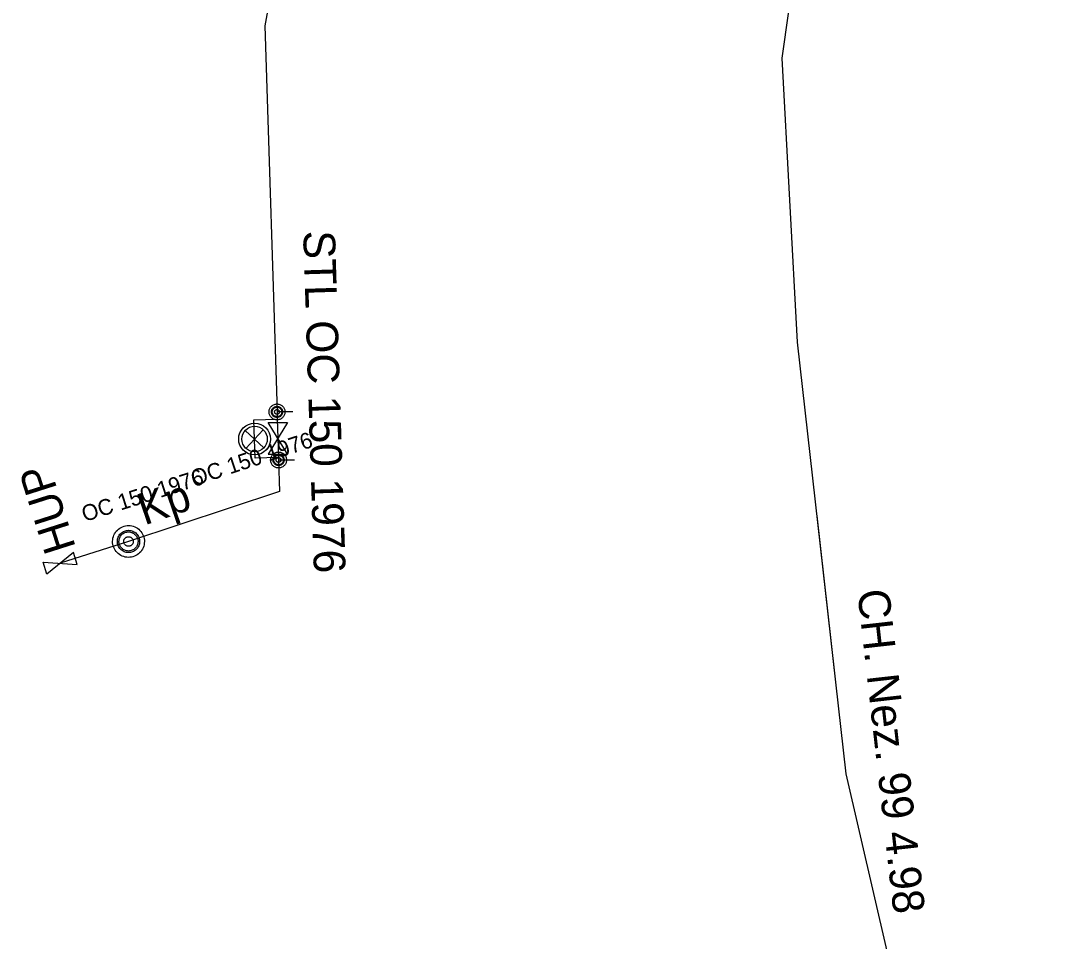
# Model space of a CAD drawing. Extents: x -743325 to -742825, y -1051501 to -1050981.
# Drawn here: x -743099.05 to -743066.36, y -1051247.7 to -1051218.76 of the extents above; entities that cross this region are included whole.
import ezdxf

# ---------------------------------------------------------------- set-up
doc = ezdxf.new("R2010")
doc.units = 0
for name, color, linetype in [('NT OP Chráni_ka - provoz', 7, 'Continuous'), ('NT Úsek plynovodu - provoz', 7, 'Continuous'), ('ST Kapák - provoz_popis', 7, 'Continuous'), ('ST Ochoz plynovodu - provoz', 7, 'Continuous'), ('ST Úsek p_ípojky - provoz', 7, 'Continuous'), ('ST Úsek plynovodu - provoz', 7, 'Continuous'), ('ST_HUP_24_popis', 7, 'Continuous'), ('Vrstva 1', 7, 'Continuous')]:
    doc.layers.add(name, color=color, linetype=linetype)

msp = doc.modelspace()

# ---------------------------------------------------------------- linework, layer by layer
at = {"layer": 'NT OP Chráni_ka - provoz'}
msp.add_lwpolyline([(-743074.013, -1051234.317), (-743073.456, -1051239.266)], dxfattribs=at)
at = {"layer": 'NT Úsek plynovodu - provoz'}
msp.add_lwpolyline([(-743070.968, -1051164.821), (-743071.535, -1051165.016), (-743070.085, -1051169.589), (-743067.096, -1051178.869), (-743066.357, -1051181.989), (-743073.395, -1051209.661), (-743074.036, -1051212.311), (-743075.117, -1051219.935), (-743074.627, -1051228.857), (-743073.099, -1051242.438), (-743069.652, -1051257.351)], dxfattribs=at)
at = {"layer": 'ST Ochoz plynovodu - provoz'}
msp.add_lwpolyline([(-743090.917, -1051232.485), (-743090.947, -1051232.485), (-743091.68, -1051232.508), (-743091.699, -1051231.908), (-743091.718, -1051231.308), (-743090.985, -1051231.285)], dxfattribs=at)
at = {"layer": 'ST Úsek p_ípojky - provoz'}
for points in [[(-743090.913, -1051233.556), (-743095.664, -1051235.128)], [(-743095.664, -1051235.128), (-743097.815, -1051235.814)]]:
    msp.add_lwpolyline(points, dxfattribs=at)
at = {"layer": 'ST Úsek plynovodu - provoz'}
for points in [[(-743072.447, -1051184.993), (-743072.908, -1051184.597), (-743077.116, -1051180.977), (-743077.49, -1051180.777), (-743085.06, -1051188.896), (-743089.578, -1051208.662), (-743091.275, -1051218.341), (-743091.375, -1051218.913)], [(-743091.375, -1051218.913), (-743090.992, -1051231.055), (-743090.985, -1051231.285), (-743090.966, -1051231.885)], [(-743090.966, -1051231.885), (-743090.947, -1051232.485), (-743090.944, -1051232.567), (-743090.913, -1051233.556)]]:
    msp.add_lwpolyline(points, dxfattribs=at)
at = {"layer": 'Vrstva 1'}
for p, q in [((-743090.492, -1051231.055), (-743090.992, -1051231.055)), ((-743091.266, -1051231.385), (-743090.666, -1051231.385)), ((-743090.666, -1051231.385), (-743091.266, -1051232.385)), ((-743090.666, -1051232.385), (-743091.266, -1051231.385)), ((-743091.992, -1051231.635), (-743091.406, -1051232.181)), ((-743091.426, -1051231.615), (-743091.972, -1051232.201)), ((-743091.266, -1051232.385), (-743090.666, -1051232.385)), ((-743090.444, -1051232.567), (-743090.944, -1051232.567))]:
    msp.add_line(p, q, dxfattribs=at)
for points in [[(-743090.742, -1051231.043), (-743090.742, -1051231.067), (-743090.745, -1051231.092), (-743090.749, -1051231.116), (-743090.757, -1051231.139), (-743090.766, -1051231.162), (-743090.777, -1051231.183), (-743090.791, -1051231.204), (-743090.807, -1051231.223), (-743090.824, -1051231.24), (-743090.843, -1051231.256), (-743090.863, -1051231.269), (-743090.885, -1051231.281), (-743090.908, -1051231.29), (-743090.931, -1051231.298), (-743090.955, -1051231.302), (-743090.98, -1051231.305), (-743091.005, -1051231.305), (-743091.029, -1051231.302), (-743091.053, -1051231.298), (-743091.077, -1051231.29), (-743091.099, -1051231.281), (-743091.121, -1051231.269), (-743091.141, -1051231.256), (-743091.16, -1051231.24), (-743091.178, -1051231.223), (-743091.193, -1051231.204), (-743091.207, -1051231.183), (-743091.218, -1051231.162), (-743091.228, -1051231.139), (-743091.235, -1051231.116), (-743091.24, -1051231.092), (-743091.242, -1051231.067), (-743091.242, -1051231.043), (-743091.24, -1051231.018), (-743091.235, -1051230.994), (-743091.228, -1051230.971), (-743091.218, -1051230.948), (-743091.207, -1051230.926), (-743091.193, -1051230.906), (-743091.178, -1051230.887), (-743091.16, -1051230.869), (-743091.141, -1051230.854), (-743091.121, -1051230.84), (-743091.099, -1051230.829), (-743091.077, -1051230.819), (-743091.053, -1051230.812), (-743091.029, -1051230.807), (-743091.005, -1051230.805), (-743090.98, -1051230.805), (-743090.955, -1051230.807), (-743090.931, -1051230.812), (-743090.908, -1051230.819), (-743090.885, -1051230.829), (-743090.863, -1051230.84), (-743090.843, -1051230.854), (-743090.824, -1051230.869), (-743090.807, -1051230.887), (-743090.791, -1051230.906), (-743090.777, -1051230.926), (-743090.766, -1051230.948), (-743090.757, -1051230.971), (-743090.749, -1051230.994), (-743090.745, -1051231.018)], [(-743091.001, -1051230.88), (-743090.984, -1051230.88), (-743090.967, -1051230.881), (-743090.95, -1051230.885), (-743090.933, -1051230.89), (-743090.917, -1051230.896), (-743090.902, -1051230.905), (-743090.888, -1051230.914), (-743090.875, -1051230.925), (-743090.862, -1051230.937), (-743090.851, -1051230.95), (-743090.842, -1051230.965), (-743090.834, -1051230.98), (-743090.827, -1051230.996), (-743090.822, -1051231.012), (-743090.819, -1051231.029), (-743090.817, -1051231.046), (-743090.817, -1051231.063), (-743090.819, -1051231.081), (-743090.822, -1051231.097), (-743090.827, -1051231.114), (-743090.834, -1051231.13), (-743090.842, -1051231.145), (-743090.851, -1051231.159), (-743090.862, -1051231.172), (-743090.875, -1051231.185), (-743090.888, -1051231.196), (-743090.902, -1051231.205), (-743090.917, -1051231.213), (-743090.933, -1051231.22), (-743090.95, -1051231.225), (-743090.967, -1051231.228), (-743090.984, -1051231.23), (-743091.001, -1051231.23), (-743091.018, -1051231.228), (-743091.035, -1051231.225), (-743091.051, -1051231.22), (-743091.067, -1051231.213), (-743091.082, -1051231.205), (-743091.097, -1051231.196), (-743091.11, -1051231.185), (-743091.122, -1051231.172), (-743091.133, -1051231.159), (-743091.143, -1051231.145), (-743091.151, -1051231.13), (-743091.157, -1051231.114), (-743091.162, -1051231.097), (-743091.165, -1051231.081), (-743091.167, -1051231.063), (-743091.167, -1051231.046), (-743091.165, -1051231.029), (-743091.162, -1051231.012), (-743091.157, -1051230.996), (-743091.151, -1051230.98), (-743091.143, -1051230.965), (-743091.133, -1051230.95), (-743091.122, -1051230.937), (-743091.11, -1051230.925), (-743091.097, -1051230.914), (-743091.082, -1051230.905), (-743091.067, -1051230.896), (-743091.051, -1051230.89), (-743091.035, -1051230.885), (-743091.018, -1051230.881)], [(-743090.985, -1051231.205), (-743091, -1051231.205), (-743091.014, -1051231.203), (-743091.029, -1051231.201), (-743091.043, -1051231.196), (-743091.056, -1051231.191), (-743091.069, -1051231.184), (-743091.082, -1051231.175), (-743091.093, -1051231.166), (-743091.103, -1051231.156), (-743091.113, -1051231.144), (-743091.121, -1051231.132), (-743091.128, -1051231.119), (-743091.134, -1051231.105), (-743091.138, -1051231.091), (-743091.141, -1051231.077), (-743091.142, -1051231.062), (-743091.142, -1051231.047), (-743091.141, -1051231.033), (-743091.138, -1051231.018), (-743091.134, -1051231.004), (-743091.128, -1051230.991), (-743091.121, -1051230.978), (-743091.113, -1051230.965), (-743091.103, -1051230.954), (-743091.093, -1051230.943), (-743091.082, -1051230.934), (-743091.069, -1051230.926), (-743091.056, -1051230.919), (-743091.043, -1051230.913), (-743091.029, -1051230.909), (-743091.014, -1051230.906), (-743091, -1051230.905), (-743090.985, -1051230.905), (-743090.97, -1051230.906), (-743090.956, -1051230.909), (-743090.942, -1051230.913), (-743090.928, -1051230.919), (-743090.915, -1051230.926), (-743090.903, -1051230.934), (-743090.891, -1051230.943), (-743090.881, -1051230.954), (-743090.872, -1051230.965), (-743090.863, -1051230.978), (-743090.856, -1051230.991), (-743090.851, -1051231.004), (-743090.847, -1051231.018), (-743090.844, -1051231.033), (-743090.842, -1051231.047), (-743090.842, -1051231.062), (-743090.844, -1051231.077), (-743090.847, -1051231.091), (-743090.851, -1051231.105), (-743090.856, -1051231.119), (-743090.863, -1051231.132), (-743090.872, -1051231.144), (-743090.881, -1051231.156), (-743090.891, -1051231.166), (-743090.903, -1051231.175), (-743090.915, -1051231.184), (-743090.928, -1051231.191), (-743090.942, -1051231.196), (-743090.956, -1051231.201), (-743090.97, -1051231.203)], [(-743090.989, -1051231.13), (-743090.996, -1051231.13), (-743091.003, -1051231.129), (-743091.01, -1051231.128), (-743091.017, -1051231.125), (-743091.024, -1051231.123), (-743091.031, -1051231.119), (-743091.037, -1051231.115), (-743091.043, -1051231.11), (-743091.048, -1051231.105), (-743091.053, -1051231.1), (-743091.057, -1051231.093), (-743091.06, -1051231.087), (-743091.063, -1051231.08), (-743091.065, -1051231.073), (-743091.067, -1051231.066), (-743091.067, -1051231.059), (-743091.067, -1051231.051), (-743091.067, -1051231.044), (-743091.065, -1051231.037), (-743091.063, -1051231.029), (-743091.06, -1051231.023), (-743091.057, -1051231.016), (-743091.053, -1051231.01), (-743091.048, -1051231.004), (-743091.043, -1051230.999), (-743091.037, -1051230.995), (-743091.031, -1051230.99), (-743091.024, -1051230.987), (-743091.017, -1051230.984), (-743091.01, -1051230.982), (-743091.003, -1051230.981), (-743090.996, -1051230.98), (-743090.989, -1051230.98), (-743090.981, -1051230.981), (-743090.974, -1051230.982), (-743090.967, -1051230.984), (-743090.96, -1051230.987), (-743090.954, -1051230.99), (-743090.947, -1051230.995), (-743090.942, -1051230.999), (-743090.937, -1051231.004), (-743090.932, -1051231.01), (-743090.928, -1051231.016), (-743090.924, -1051231.023), (-743090.921, -1051231.029), (-743090.919, -1051231.037), (-743090.918, -1051231.044), (-743090.917, -1051231.051), (-743090.917, -1051231.059), (-743090.918, -1051231.066), (-743090.919, -1051231.073), (-743090.921, -1051231.08), (-743090.924, -1051231.087), (-743090.928, -1051231.093), (-743090.932, -1051231.1), (-743090.937, -1051231.105), (-743090.942, -1051231.11), (-743090.947, -1051231.115), (-743090.954, -1051231.119), (-743090.96, -1051231.123), (-743090.967, -1051231.125), (-743090.974, -1051231.128), (-743090.981, -1051231.129)], [(-743090.694, -1051232.555), (-743090.694, -1051232.579), (-743090.697, -1051232.604), (-743090.701, -1051232.628), (-743090.709, -1051232.651), (-743090.718, -1051232.674), (-743090.729, -1051232.695), (-743090.743, -1051232.716), (-743090.759, -1051232.735), (-743090.776, -1051232.752), (-743090.795, -1051232.768), (-743090.815, -1051232.781), (-743090.837, -1051232.793), (-743090.86, -1051232.802), (-743090.883, -1051232.81), (-743090.907, -1051232.814), (-743090.932, -1051232.817), (-743090.957, -1051232.817), (-743090.981, -1051232.814), (-743091.005, -1051232.81), (-743091.029, -1051232.802), (-743091.051, -1051232.793), (-743091.073, -1051232.781), (-743091.093, -1051232.768), (-743091.112, -1051232.752), (-743091.13, -1051232.735), (-743091.145, -1051232.716), (-743091.159, -1051232.695), (-743091.17, -1051232.674), (-743091.18, -1051232.651), (-743091.187, -1051232.628), (-743091.192, -1051232.604), (-743091.194, -1051232.579), (-743091.194, -1051232.555), (-743091.192, -1051232.53), (-743091.187, -1051232.506), (-743091.18, -1051232.483), (-743091.17, -1051232.46), (-743091.159, -1051232.438), (-743091.145, -1051232.418), (-743091.13, -1051232.399), (-743091.112, -1051232.381), (-743091.093, -1051232.366), (-743091.073, -1051232.352), (-743091.051, -1051232.341), (-743091.029, -1051232.331), (-743091.005, -1051232.324), (-743090.981, -1051232.319), (-743090.957, -1051232.317), (-743090.932, -1051232.317), (-743090.907, -1051232.319), (-743090.883, -1051232.324), (-743090.86, -1051232.331), (-743090.837, -1051232.341), (-743090.815, -1051232.352), (-743090.795, -1051232.366), (-743090.776, -1051232.381), (-743090.759, -1051232.399), (-743090.743, -1051232.418), (-743090.729, -1051232.438), (-743090.718, -1051232.46), (-743090.709, -1051232.483), (-743090.701, -1051232.506), (-743090.697, -1051232.53)], [(-743090.953, -1051232.392), (-743090.936, -1051232.392), (-743090.919, -1051232.393), (-743090.902, -1051232.397), (-743090.885, -1051232.402), (-743090.869, -1051232.408), (-743090.854, -1051232.417), (-743090.84, -1051232.426), (-743090.827, -1051232.437), (-743090.814, -1051232.449), (-743090.803, -1051232.462), (-743090.794, -1051232.477), (-743090.786, -1051232.492), (-743090.779, -1051232.508), (-743090.774, -1051232.524), (-743090.771, -1051232.541), (-743090.769, -1051232.558), (-743090.769, -1051232.575), (-743090.771, -1051232.593), (-743090.774, -1051232.609), (-743090.779, -1051232.626), (-743090.786, -1051232.642), (-743090.794, -1051232.657), (-743090.803, -1051232.671), (-743090.814, -1051232.684), (-743090.827, -1051232.697), (-743090.84, -1051232.708), (-743090.854, -1051232.717), (-743090.869, -1051232.725), (-743090.885, -1051232.732), (-743090.902, -1051232.737), (-743090.919, -1051232.74), (-743090.936, -1051232.742), (-743090.953, -1051232.742), (-743090.97, -1051232.74), (-743090.987, -1051232.737), (-743091.003, -1051232.732), (-743091.019, -1051232.725), (-743091.034, -1051232.717), (-743091.049, -1051232.708), (-743091.062, -1051232.697), (-743091.074, -1051232.684), (-743091.085, -1051232.671), (-743091.095, -1051232.657), (-743091.103, -1051232.642), (-743091.109, -1051232.626), (-743091.114, -1051232.609), (-743091.117, -1051232.593), (-743091.119, -1051232.575), (-743091.119, -1051232.558), (-743091.117, -1051232.541), (-743091.114, -1051232.524), (-743091.109, -1051232.508), (-743091.103, -1051232.492), (-743091.095, -1051232.477), (-743091.085, -1051232.462), (-743091.074, -1051232.449), (-743091.062, -1051232.437), (-743091.049, -1051232.426), (-743091.034, -1051232.417), (-743091.019, -1051232.408), (-743091.003, -1051232.402), (-743090.987, -1051232.397), (-743090.97, -1051232.393)], [(-743090.937, -1051232.717), (-743090.952, -1051232.717), (-743090.966, -1051232.715), (-743090.981, -1051232.713), (-743090.995, -1051232.708), (-743091.008, -1051232.703), (-743091.021, -1051232.696), (-743091.034, -1051232.687), (-743091.045, -1051232.678), (-743091.055, -1051232.668), (-743091.065, -1051232.656), (-743091.073, -1051232.644), (-743091.08, -1051232.631), (-743091.086, -1051232.617), (-743091.09, -1051232.603), (-743091.093, -1051232.589), (-743091.094, -1051232.574), (-743091.094, -1051232.559), (-743091.093, -1051232.545), (-743091.09, -1051232.53), (-743091.086, -1051232.516), (-743091.08, -1051232.503), (-743091.073, -1051232.49), (-743091.065, -1051232.477), (-743091.055, -1051232.466), (-743091.045, -1051232.455), (-743091.034, -1051232.446), (-743091.021, -1051232.438), (-743091.008, -1051232.431), (-743090.995, -1051232.425), (-743090.981, -1051232.421), (-743090.966, -1051232.418), (-743090.952, -1051232.417), (-743090.937, -1051232.417), (-743090.922, -1051232.418), (-743090.908, -1051232.421), (-743090.894, -1051232.425), (-743090.88, -1051232.431), (-743090.867, -1051232.438), (-743090.855, -1051232.446), (-743090.843, -1051232.455), (-743090.833, -1051232.466), (-743090.824, -1051232.477), (-743090.815, -1051232.49), (-743090.808, -1051232.503), (-743090.803, -1051232.516), (-743090.799, -1051232.53), (-743090.796, -1051232.545), (-743090.794, -1051232.559), (-743090.794, -1051232.574), (-743090.796, -1051232.589), (-743090.799, -1051232.603), (-743090.803, -1051232.617), (-743090.808, -1051232.631), (-743090.815, -1051232.644), (-743090.824, -1051232.656), (-743090.833, -1051232.668), (-743090.843, -1051232.678), (-743090.855, -1051232.687), (-743090.867, -1051232.696), (-743090.88, -1051232.703), (-743090.894, -1051232.708), (-743090.908, -1051232.713), (-743090.922, -1051232.715)], [(-743090.941, -1051232.642), (-743090.948, -1051232.642), (-743090.955, -1051232.641), (-743090.962, -1051232.64), (-743090.969, -1051232.637), (-743090.976, -1051232.635), (-743090.983, -1051232.631), (-743090.989, -1051232.627), (-743090.995, -1051232.622), (-743091, -1051232.617), (-743091.005, -1051232.612), (-743091.009, -1051232.605), (-743091.012, -1051232.599), (-743091.015, -1051232.592), (-743091.017, -1051232.585), (-743091.019, -1051232.578), (-743091.019, -1051232.571), (-743091.019, -1051232.563), (-743091.019, -1051232.556), (-743091.017, -1051232.549), (-743091.015, -1051232.541), (-743091.012, -1051232.535), (-743091.009, -1051232.528), (-743091.005, -1051232.522), (-743091, -1051232.516), (-743090.995, -1051232.511), (-743090.989, -1051232.507), (-743090.983, -1051232.502), (-743090.976, -1051232.499), (-743090.969, -1051232.496), (-743090.962, -1051232.494), (-743090.955, -1051232.493), (-743090.948, -1051232.492), (-743090.941, -1051232.492), (-743090.933, -1051232.493), (-743090.926, -1051232.494), (-743090.919, -1051232.496), (-743090.912, -1051232.499), (-743090.906, -1051232.502), (-743090.899, -1051232.507), (-743090.894, -1051232.511), (-743090.889, -1051232.516), (-743090.884, -1051232.522), (-743090.88, -1051232.528), (-743090.876, -1051232.535), (-743090.873, -1051232.541), (-743090.871, -1051232.549), (-743090.87, -1051232.556), (-743090.869, -1051232.563), (-743090.869, -1051232.571), (-743090.87, -1051232.578), (-743090.871, -1051232.585), (-743090.873, -1051232.592), (-743090.876, -1051232.599), (-743090.88, -1051232.605), (-743090.884, -1051232.612), (-743090.889, -1051232.617), (-743090.894, -1051232.622), (-743090.899, -1051232.627), (-743090.906, -1051232.631), (-743090.912, -1051232.635), (-743090.919, -1051232.637), (-743090.926, -1051232.64), (-743090.933, -1051232.641)], [(-743095.85, -1051234.663), (-743095.804, -1051234.647), (-743095.756, -1051234.636), (-743095.708, -1051234.629), (-743095.658, -1051234.628), (-743095.609, -1051234.631), (-743095.561, -1051234.639), (-743095.513, -1051234.651), (-743095.467, -1051234.668), (-743095.423, -1051234.69), (-743095.381, -1051234.715), (-743095.342, -1051234.745), (-743095.306, -1051234.779), (-743095.274, -1051234.815), (-743095.245, -1051234.855), (-743095.22, -1051234.897), (-743095.199, -1051234.942), (-743095.183, -1051234.989), (-743095.172, -1051235.037), (-743095.166, -1051235.085), (-743095.164, -1051235.134), (-743095.167, -1051235.183), (-743095.175, -1051235.231), (-743095.187, -1051235.279), (-743095.204, -1051235.325), (-743095.226, -1051235.369), (-743095.251, -1051235.411), (-743095.281, -1051235.45), (-743095.315, -1051235.486), (-743095.352, -1051235.519), (-743095.391, -1051235.548), (-743095.434, -1051235.572), (-743095.479, -1051235.593), (-743095.525, -1051235.609), (-743095.573, -1051235.62), (-743095.621, -1051235.627), (-743095.67, -1051235.628), (-743095.719, -1051235.625), (-743095.768, -1051235.618), (-743095.815, -1051235.605), (-743095.861, -1051235.588), (-743095.905, -1051235.566), (-743095.947, -1051235.541), (-743095.987, -1051235.511), (-743096.023, -1051235.478), (-743096.055, -1051235.441), (-743096.084, -1051235.402), (-743096.108, -1051235.359), (-743096.129, -1051235.314), (-743096.145, -1051235.267), (-743096.156, -1051235.219), (-743096.163, -1051235.171), (-743096.165, -1051235.122), (-743096.162, -1051235.073), (-743096.154, -1051235.025), (-743096.141, -1051234.977), (-743096.124, -1051234.931), (-743096.102, -1051234.887), (-743096.077, -1051234.845), (-743096.048, -1051234.806), (-743096.013, -1051234.77), (-743095.977, -1051234.738), (-743095.938, -1051234.708), (-743095.895, -1051234.684)], [(-743095.989, -1051235.258), (-743096, -1051235.226), (-743096.009, -1051235.193), (-743096.013, -1051235.158), (-743096.014, -1051235.124), (-743096.013, -1051235.089), (-743096.007, -1051235.056), (-743095.999, -1051235.022), (-743095.986, -1051234.99), (-743095.972, -1051234.959), (-743095.953, -1051234.929), (-743095.932, -1051234.902), (-743095.909, -1051234.877), (-743095.883, -1051234.854), (-743095.855, -1051234.834), (-743095.826, -1051234.817), (-743095.794, -1051234.803), (-743095.762, -1051234.792), (-743095.729, -1051234.783), (-743095.694, -1051234.779), (-743095.66, -1051234.778), (-743095.625, -1051234.779), (-743095.592, -1051234.785), (-743095.559, -1051234.794), (-743095.526, -1051234.806), (-743095.496, -1051234.821), (-743095.466, -1051234.839), (-743095.439, -1051234.86), (-743095.413, -1051234.883), (-743095.39, -1051234.909), (-743095.37, -1051234.937), (-743095.353, -1051234.967), (-743095.339, -1051234.998), (-743095.328, -1051235.03), (-743095.32, -1051235.064), (-743095.315, -1051235.098), (-743095.314, -1051235.132), (-743095.315, -1051235.167), (-743095.322, -1051235.201), (-743095.33, -1051235.234), (-743095.343, -1051235.266), (-743095.357, -1051235.297), (-743095.376, -1051235.327), (-743095.396, -1051235.354), (-743095.419, -1051235.379), (-743095.445, -1051235.402), (-743095.473, -1051235.422), (-743095.503, -1051235.439), (-743095.534, -1051235.453), (-743095.566, -1051235.464), (-743095.6, -1051235.473), (-743095.634, -1051235.477), (-743095.668, -1051235.478), (-743095.703, -1051235.477), (-743095.736, -1051235.471), (-743095.77, -1051235.463), (-743095.802, -1051235.451), (-743095.833, -1051235.435), (-743095.863, -1051235.417), (-743095.89, -1051235.396), (-743095.915, -1051235.373), (-743095.938, -1051235.347), (-743095.958, -1051235.319), (-743095.975, -1051235.289)], [(-743095.385, -1051235.016), (-743095.375, -1051235.045), (-743095.369, -1051235.073), (-743095.365, -1051235.102), (-743095.364, -1051235.131), (-743095.366, -1051235.161), (-743095.371, -1051235.19), (-743095.378, -1051235.219), (-743095.388, -1051235.247), (-743095.4, -1051235.273), (-743095.416, -1051235.298), (-743095.434, -1051235.322), (-743095.454, -1051235.344), (-743095.476, -1051235.363), (-743095.5, -1051235.379), (-743095.526, -1051235.394), (-743095.553, -1051235.407), (-743095.581, -1051235.417), (-743095.609, -1051235.423), (-743095.638, -1051235.427), (-743095.667, -1051235.428), (-743095.697, -1051235.427), (-743095.727, -1051235.422), (-743095.755, -1051235.414), (-743095.782, -1051235.405), (-743095.809, -1051235.392), (-743095.835, -1051235.376), (-743095.858, -1051235.358), (-743095.88, -1051235.338), (-743095.899, -1051235.316), (-743095.916, -1051235.292), (-743095.93, -1051235.266), (-743095.943, -1051235.24), (-743095.953, -1051235.211), (-743095.959, -1051235.183), (-743095.964, -1051235.154), (-743095.964, -1051235.125), (-743095.963, -1051235.096), (-743095.958, -1051235.066), (-743095.951, -1051235.038), (-743095.941, -1051235.01), (-743095.928, -1051234.983), (-743095.912, -1051234.958), (-743095.895, -1051234.935), (-743095.875, -1051234.913), (-743095.852, -1051234.893), (-743095.828, -1051234.877), (-743095.802, -1051234.862), (-743095.776, -1051234.849), (-743095.748, -1051234.84), (-743095.719, -1051234.833), (-743095.69, -1051234.829), (-743095.661, -1051234.828), (-743095.632, -1051234.829), (-743095.602, -1051234.834), (-743095.573, -1051234.842), (-743095.546, -1051234.851), (-743095.52, -1051234.865), (-743095.494, -1051234.88), (-743095.471, -1051234.899), (-743095.449, -1051234.919), (-743095.429, -1051234.94), (-743095.413, -1051234.964), (-743095.398, -1051234.99)], [(-743095.524, -1051235.073), (-743095.52, -1051235.086), (-743095.517, -1051235.101), (-743095.514, -1051235.115), (-743095.514, -1051235.13), (-743095.515, -1051235.144), (-743095.517, -1051235.159), (-743095.521, -1051235.174), (-743095.526, -1051235.187), (-743095.532, -1051235.2), (-743095.54, -1051235.213), (-743095.549, -1051235.225), (-743095.559, -1051235.236), (-743095.571, -1051235.245), (-743095.582, -1051235.254), (-743095.595, -1051235.262), (-743095.609, -1051235.268), (-743095.623, -1051235.272), (-743095.636, -1051235.276), (-743095.651, -1051235.278), (-743095.666, -1051235.278), (-743095.68, -1051235.277), (-743095.695, -1051235.275), (-743095.71, -1051235.272), (-743095.723, -1051235.266), (-743095.737, -1051235.26), (-743095.749, -1051235.252), (-743095.761, -1051235.243), (-743095.772, -1051235.233), (-743095.782, -1051235.222), (-743095.79, -1051235.21), (-743095.798, -1051235.197), (-743095.804, -1051235.183), (-743095.808, -1051235.17), (-743095.812, -1051235.156), (-743095.814, -1051235.141), (-743095.815, -1051235.126), (-743095.813, -1051235.112), (-743095.811, -1051235.097), (-743095.808, -1051235.082), (-743095.803, -1051235.069), (-743095.796, -1051235.056), (-743095.788, -1051235.043), (-743095.779, -1051235.031), (-743095.769, -1051235.02), (-743095.758, -1051235.011), (-743095.747, -1051235.002), (-743095.733, -1051234.994), (-743095.72, -1051234.989), (-743095.706, -1051234.984), (-743095.692, -1051234.98), (-743095.677, -1051234.978), (-743095.663, -1051234.978), (-743095.648, -1051234.979), (-743095.633, -1051234.981), (-743095.619, -1051234.985), (-743095.605, -1051234.99), (-743095.592, -1051234.996), (-743095.58, -1051235.004), (-743095.567, -1051235.013), (-743095.556, -1051235.023), (-743095.547, -1051235.034), (-743095.538, -1051235.046), (-743095.531, -1051235.059)]]:
    msp.add_lwpolyline(points, close=True, dxfattribs=at)
msp.add_lwpolyline([(-743098.231, -1051236.156), (-743098.352, -1051235.775), (-743097.278, -1051235.853), (-743097.399, -1051235.472), (-743098.231, -1051236.156)], dxfattribs=at)
for radius in [0.5, 0.4]:
    msp.add_circle((-743091.699, -1051231.908), radius, dxfattribs=at)

# ---------------------------------------------------------------- texts
at = {"layer": 'NT OP Chráni_ka - provoz'}
msp.add_text('CH. Nez. 99 4.98', height=1, rotation=276.4215, dxfattribs=at).set_placement((-743072.741, -1051236.68))
at = {"layer": 'ST Kapák - provoz_popis'}
msp.add_text('Kp', height=1, rotation=19, dxfattribs=at).set_placement((-743095.164, -1051234.628))
at = {"layer": 'ST Úsek p_ípojky - provoz'}
for rotation, p in [(18.3082, (-743093.603, -1051233.393)), (17.6886, (-743097.043, -1051234.518))]:
    msp.add_text('OC 150 1976', height=0.5, rotation=rotation, dxfattribs=at).set_placement(p)
at = {"layer": 'ST Úsek plynovodu - provoz'}
msp.add_text('STL OC 150 1976', height=1, rotation=271.8067, dxfattribs=at).set_placement((-743090.171, -1051225.367))
at = {"layer": 'ST_HUP_24_popis'}
msp.add_text('HUP', height=1, rotation=107.69, dxfattribs=at).set_placement((-743097.315, -1051235.314))

doc.saveas('drawing.dxf')
